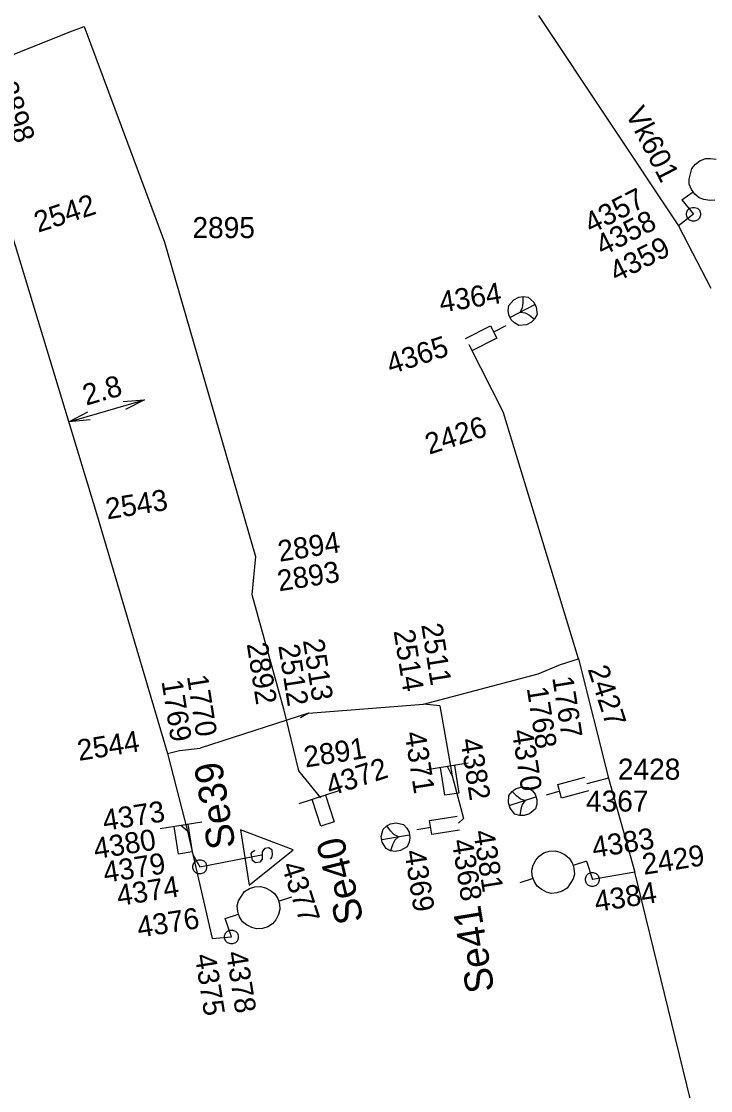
# Model space of a CAD drawing. Extents: x -535557 to -534097, y -1142175 to -1136716.
# Drawn here: x -534945.19 to -534920.6, y -1139009.65 to -1138971.51 of the extents above; entities that cross this region are included whole.
import ezdxf

# ---------------------------------------------------------------- set-up
doc = ezdxf.new("R2010")
doc.units = 0
doc.layers.add('Default', color=7, linetype='Continuous')
doc.layers.add('SS_SZDC', color=7, linetype='Continuous')

# ---------------------------------------------------------------- blocks, each defined once
blk = doc.blocks.new('POINT_DISPLAY')
at = {"layer": 'Default'}
blk.add_line((0, 0), (0, 0), dxfattribs=at)

msp = doc.modelspace()

# ---------------------------------------------------------------- linework, layer by layer
at = {"layer": 'SS_SZDC'}
for p, q in [((-534926.739, -1138971.299), (-534921.739, -1138978.799)), ((-534943.46, -1138971.879), (-534942.949, -1138971.69)), ((-534942.949, -1138971.69), (-534940.09, -1138979.389)), ((-534946.289, -1138973.01), (-534943.46, -1138971.879)), ((-534921.272, -1138976.755), (-534921.14, -1138976.597)), ((-534921.14, -1138976.597), (-534920.978, -1138976.479)), ((-534920.978, -1138976.479), (-534920.787, -1138976.402)), ((-534920.787, -1138976.402), (-534920.607, -1138976.395)), ((-534920.607, -1138976.395), (-534920.397, -1138976.428)), ((-534921.368, -1138977.133), (-534921.272, -1138976.755)), ((-534921.361, -1138977.314), (-534921.368, -1138977.133)), ((-534921.284, -1138977.505), (-534921.361, -1138977.314)), ((-534921.63, -1138977.879), (-534921.225, -1138977.586)), ((-534921.225, -1138977.586), (-534921.284, -1138977.505)), ((-534921.166, -1138977.667), (-534921.225, -1138977.586)), ((-534921.008, -1138977.799), (-534921.166, -1138977.667)), ((-534920.839, -1138977.861), (-534921.008, -1138977.799)), ((-534921.63, -1138977.879), (-534921.21, -1138978.389)), ((-534921.422, -1138978.248), (-534921.351, -1138978.177)), ((-534921.351, -1138978.177), (-534921.245, -1138978.142)), ((-534921.245, -1138978.142), (-534921.174, -1138978.142)), ((-534921.174, -1138978.142), (-534921.068, -1138978.177)), ((-534921.068, -1138978.177), (-534920.997, -1138978.248)), ((-534920.63, -1138977.895), (-534920.839, -1138977.861)), ((-534920.449, -1138977.887), (-534920.63, -1138977.895)), ((-534921.21, -1138978.389), (-534921.739, -1138978.799)), ((-534921.457, -1138978.354), (-534921.422, -1138978.248)), ((-534921.457, -1138978.425), (-534921.457, -1138978.354)), ((-534921.422, -1138978.531), (-534921.457, -1138978.425)), ((-534921.351, -1138978.602), (-534921.422, -1138978.531)), ((-534920.997, -1138978.531), (-534921.068, -1138978.602)), ((-534920.997, -1138978.248), (-534920.962, -1138978.354)), ((-534920.962, -1138978.425), (-534920.997, -1138978.531)), ((-534920.962, -1138978.354), (-534920.962, -1138978.425)), ((-534921.739, -1138978.799), (-534920.59, -1138981.03)), ((-534921.245, -1138978.637), (-534921.351, -1138978.602)), ((-534921.174, -1138978.637), (-534921.245, -1138978.637)), ((-534921.068, -1138978.602), (-534921.174, -1138978.637)), ((-534945.529, -1138979.11), (-534942.51, -1138989.059)), ((-534940.09, -1138979.389), (-534936.84, -1138990.6)), ((-534927.803, -1138981.642), (-534927.626, -1138981.439)), ((-534926.864, -1138981.613), (-534927.755, -1138982.066)), ((-534927.626, -1138981.439), (-534927.447, -1138981.349)), ((-534927.447, -1138981.349), (-534927.291, -1138981.325)), ((-534927.31, -1138981.728), (-534927.289, -1138981.549)), ((-534927.291, -1138981.325), (-534927.112, -1138981.346)), ((-534927.289, -1138981.549), (-534927.291, -1138981.325)), ((-534927.112, -1138981.346), (-534926.909, -1138981.523)), ((-534926.909, -1138981.523), (-534926.819, -1138981.702)), ((-534927.824, -1138981.821), (-534927.803, -1138981.642)), ((-534927.8, -1138981.977), (-534927.824, -1138981.821)), ((-534927.71, -1138982.156), (-534927.8, -1138981.977)), ((-534927.399, -1138981.885), (-534927.31, -1138981.728)), ((-534927.399, -1138981.885), (-534927.22, -1138981.906)), ((-534927.22, -1138981.906), (-534927.062, -1138981.994)), ((-534927.062, -1138981.994), (-534926.882, -1138982.127)), ((-534926.794, -1138981.97), (-534926.882, -1138982.127)), ((-534926.819, -1138981.702), (-534926.794, -1138981.97)), ((-534929.343, -1138982.817), (-534928.452, -1138982.363)), ((-534928.452, -1138982.363), (-534928.225, -1138982.808)), ((-534928.338, -1138982.586), (-534927.893, -1138982.359)), ((-534927.597, -1138982.267), (-534927.71, -1138982.156)), ((-534927.44, -1138982.355), (-534927.597, -1138982.267)), ((-534927.172, -1138982.33), (-534927.44, -1138982.355)), ((-534926.993, -1138982.24), (-534927.172, -1138982.33)), ((-534926.882, -1138982.127), (-534926.993, -1138982.24)), ((-534929.229, -1138983.04), (-534927.989, -1138985.469)), ((-534928.225, -1138982.808), (-534929.116, -1138983.262)), ((-534943.502, -1138985.789), (-534940.798, -1138985.007)), ((-534941.56, -1138985.071), (-534940.798, -1138985.007)), ((-534940.798, -1138985.007), (-534941.477, -1138985.359)), ((-534943.502, -1138985.789), (-534942.823, -1138985.436)), ((-534942.74, -1138985.724), (-534943.502, -1138985.789)), ((-534925.319, -1138994.25), (-534927.989, -1138985.469)), ((-534942.51, -1138989.059), (-534939.979, -1138997.629)), ((-534936.84, -1138990.6), (-534936.97, -1138991.95)), ((-534936.97, -1138991.95), (-534935.84, -1138996.03)), ((-534926.75, -1138994.78), (-534925.96, -1138994.45)), ((-534925.96, -1138994.45), (-534925.319, -1138994.25)), ((-534925.319, -1138994.25), (-534924.239, -1138998.5)), ((-534930.85, -1138995.86), (-534926.75, -1138994.78)), ((-534935.84, -1138996.03), (-534935.31, -1138998.239)), ((-534934.949, -1138996.18), (-534930.85, -1138995.86)), ((-534930.26, -1138995.92), (-534930.85, -1138995.86)), ((-534930.26, -1138995.92), (-534929.819, -1138998.42)), ((-534934.949, -1138996.18), (-534938.819, -1138997.44)), ((-534934.949, -1138996.18), (-534935.229, -1138996.35)), ((-534939.979, -1138997.629), (-534939.55, -1138997.52)), ((-534939.979, -1138997.629), (-534939.26, -1139000.399)), ((-534939.55, -1138997.52), (-534938.819, -1138997.44)), ((-534929.249, -1138997.972), (-534930.73, -1138998.207)), ((-534935.31, -1138998.239), (-534934.52, -1138999.2)), ((-534930.08, -1138999.116), (-534930.236, -1138998.129)), ((-534929.819, -1138998.42), (-534929.989, -1138998.09)), ((-534929.743, -1138998.05), (-534929.586, -1138999.038)), ((-534929.819, -1138998.42), (-534929.42, -1138999.94)), ((-534926.05, -1138998.732), (-534925.085, -1138998.468)), ((-534925.918, -1138999.215), (-534926.05, -1138998.732)), ((-534924.239, -1138998.5), (-534925.02, -1138998.709)), ((-534924.239, -1138998.5), (-534923.3, -1139001.86)), ((-534933.866, -1138998.958), (-534935.293, -1138999.421)), ((-534934.342, -1138999.112), (-534934.033, -1139000.063)), ((-534929.586, -1138999.038), (-534930.08, -1138999.116)), ((-534927.816, -1138999.389), (-534927.798, -1138999.12)), ((-534927.798, -1138999.12), (-534927.686, -1138998.979)), ((-534927.686, -1138998.979), (-534927.559, -1138998.885)), ((-534927.529, -1138999.138), (-534927.686, -1138998.979)), ((-534927.559, -1138998.885), (-534927.369, -1138998.823)), ((-534927.388, -1138999.25), (-534927.529, -1138999.138)), ((-534927.369, -1138998.823), (-534927.1, -1138998.841)), ((-534927.1, -1138998.841), (-534926.959, -1138998.953)), ((-534926.959, -1138998.953), (-534926.865, -1138999.08)), ((-534926.865, -1138999.08), (-534926.803, -1138999.27)), ((-534925.984, -1138998.973), (-534926.466, -1138999.105)), ((-534924.954, -1138998.951), (-534925.918, -1138999.215)), ((-534934.508, -1139000.218), (-534934.817, -1138999.267)), ((-534927.754, -1138999.579), (-534927.816, -1138999.389)), ((-534927.785, -1138999.484), (-534926.834, -1138999.175)), ((-534927.214, -1138999.299), (-534927.388, -1138999.25)), ((-534927.326, -1138999.44), (-534927.375, -1138999.614)), ((-534927.214, -1138999.299), (-534927.326, -1138999.44)), ((-534926.804, -1138999.428), (-534926.853, -1138999.602)), ((-534926.803, -1138999.27), (-534926.804, -1138999.428)), ((-534930.626, -1139000.019), (-534929.639, -1138999.863)), ((-534927.582, -1138999.786), (-534927.754, -1138999.579)), ((-534927.408, -1138999.835), (-534927.582, -1138999.786)), ((-534927.375, -1138999.614), (-534927.408, -1138999.835)), ((-534927.25, -1138999.836), (-534927.408, -1138999.835)), ((-534927.06, -1138999.774), (-534927.25, -1138999.836)), ((-534926.853, -1138999.602), (-534927.06, -1138999.774)), ((-534938.759, -1139000.072), (-534940.24, -1139000.307)), ((-534939.59, -1139001.216), (-534939.746, -1139000.229)), ((-534939.26, -1139000.399), (-534939.5, -1139000.19)), ((-534939.253, -1139000.15), (-534939.096, -1139001.138)), ((-534934.033, -1139000.063), (-534934.508, -1139000.218)), ((-534932.289, -1139000.326), (-534932.157, -1139000.204)), ((-534932.157, -1139000.204), (-534932.016, -1139000.131)), ((-534932.027, -1139000.386), (-534932.157, -1139000.204)), ((-534932.016, -1139000.131), (-534931.819, -1139000.1)), ((-534931.819, -1139000.1), (-534931.556, -1139000.16)), ((-534931.556, -1139000.16), (-534931.434, -1139000.292)), ((-534931.434, -1139000.292), (-534931.361, -1139000.433)), ((-534930.587, -1139000.266), (-534931.081, -1139000.344)), ((-534930.548, -1139000.513), (-534930.626, -1139000.019)), ((-534929.42, -1138999.94), (-534929.6, -1139000.11)), ((-534939.26, -1139000.399), (-534939.079, -1139001.229)), ((-534937.379, -1139000.346), (-534937.066, -1139002.321)), ((-534935.494, -1139001.06), (-534937.379, -1139000.346)), ((-534932.349, -1139000.589), (-534932.289, -1139000.326)), ((-534932.318, -1139000.786), (-534932.349, -1139000.589)), ((-534932.333, -1139000.688), (-534931.346, -1139000.531)), ((-534931.905, -1139000.519), (-534932.027, -1139000.386)), ((-534931.741, -1139000.594), (-534931.905, -1139000.519)), ((-534931.741, -1139000.594), (-534931.873, -1139000.716)), ((-534931.361, -1139000.433), (-534931.33, -1139000.63)), ((-534931.33, -1139000.63), (-534931.356, -1139000.786)), ((-534929.56, -1139000.356), (-534930.548, -1139000.513)), ((-534937.066, -1139002.321), (-534935.494, -1139001.06)), ((-534936.513, -1139001.018), (-534936.596, -1139001.133)), ((-534936.364, -1139000.995), (-534936.513, -1139001.018)), ((-534936.25, -1139001.078), (-534936.364, -1139000.995)), ((-534932.18, -1139001.018), (-534932.318, -1139000.786)), ((-534932.016, -1139001.093), (-534932.18, -1139001.018)), ((-534931.949, -1139000.88), (-534932.016, -1139001.093)), ((-534931.873, -1139000.716), (-534931.949, -1139000.88)), ((-534931.431, -1139000.95), (-534931.663, -1139001.088)), ((-534931.356, -1139000.786), (-534931.431, -1139000.95)), ((-534939.096, -1139001.138), (-534939.59, -1139001.216)), ((-534939.079, -1139001.229), (-534938.38, -1139004.219)), ((-534939.079, -1139001.229), (-534938.829, -1139001.67)), ((-534938.971, -1139001.457), (-534938.865, -1139001.422)), ((-534938.865, -1139001.422), (-534938.794, -1139001.422)), ((-534938.829, -1139001.67), (-534936.63, -1139001.239)), ((-534938.794, -1139001.422), (-534938.688, -1139001.457)), ((-534936.991, -1139001.195), (-534936.949, -1139001.138)), ((-534936.952, -1139001.442), (-534936.991, -1139001.195)), ((-534936.837, -1139001.526), (-534936.952, -1139001.442)), ((-534936.949, -1139001.138), (-534936.858, -1139001.073)), ((-534936.606, -1139001.388), (-534936.689, -1139001.502)), ((-534936.596, -1139001.133), (-534936.606, -1139001.388)), ((-534936.302, -1139001.39), (-534936.26, -1139001.333)), ((-534936.26, -1139001.333), (-534936.227, -1139001.226)), ((-534936.227, -1139001.226), (-534936.25, -1139001.078)), ((-534931.86, -1139001.119), (-534932.016, -1139001.093)), ((-534931.663, -1139001.088), (-534931.86, -1139001.119)), ((-534926.928, -1139001.613), (-534926.832, -1139001.424)), ((-534926.832, -1139001.424), (-534926.72, -1139001.283)), ((-534926.72, -1139001.283), (-534926.545, -1139001.173)), ((-534926.545, -1139001.173), (-534926.355, -1139001.112)), ((-534926.355, -1139001.112), (-534926.149, -1139001.097)), ((-534926.149, -1139001.097), (-534925.976, -1139001.146)), ((-534925.976, -1139001.146), (-534925.787, -1139001.242)), ((-534925.787, -1139001.242), (-534925.645, -1139001.354)), ((-534925.645, -1139001.354), (-534925.536, -1139001.529)), ((-534939.077, -1139001.634), (-534939.042, -1139001.528)), ((-534939.077, -1139001.705), (-534939.077, -1139001.634)), ((-534939.042, -1139001.811), (-534939.077, -1139001.705)), ((-534939.042, -1139001.528), (-534938.971, -1139001.457)), ((-534938.971, -1139001.882), (-534939.042, -1139001.811)), ((-534938.688, -1139001.457), (-534938.617, -1139001.528)), ((-534938.617, -1139001.811), (-534938.688, -1139001.882)), ((-534938.617, -1139001.528), (-534938.582, -1139001.634)), ((-534938.582, -1139001.705), (-534938.617, -1139001.811)), ((-534938.582, -1139001.634), (-534938.582, -1139001.705)), ((-534936.689, -1139001.502), (-534936.837, -1139001.526)), ((-534926.977, -1139001.787), (-534926.928, -1139001.613)), ((-534926.963, -1139001.992), (-534926.977, -1139001.787)), ((-534925.536, -1139001.529), (-534925.505, -1139001.624)), ((-534925.029, -1139001.469), (-534925.505, -1139001.624)), ((-534925.505, -1139001.624), (-534925.474, -1139001.719)), ((-534925.474, -1139001.719), (-534925.46, -1139001.925)), ((-534925.029, -1139001.469), (-534924.819, -1139002.12)), ((-534938.865, -1139001.917), (-534938.971, -1139001.882)), ((-534938.794, -1139001.917), (-534938.865, -1139001.917)), ((-534938.688, -1139001.882), (-534938.794, -1139001.917)), ((-534926.932, -1139002.088), (-534927.407, -1139002.242)), ((-534926.901, -1139002.183), (-534926.963, -1139001.992)), ((-534926.791, -1139002.357), (-534926.901, -1139002.183)), ((-534925.509, -1139002.098), (-534925.717, -1139002.429)), ((-534925.46, -1139001.925), (-534925.509, -1139002.098)), ((-534925.067, -1139002.084), (-534925.032, -1139001.978)), ((-534925.067, -1139002.155), (-534925.067, -1139002.084)), ((-534925.032, -1139002.261), (-534925.067, -1139002.155)), ((-534925.032, -1139001.978), (-534924.961, -1139001.907)), ((-534924.961, -1139001.907), (-534924.855, -1139001.872)), ((-534924.855, -1139001.872), (-534924.784, -1139001.872)), ((-534923.3, -1139001.86), (-534924.819, -1139002.12)), ((-534924.784, -1139001.872), (-534924.678, -1139001.907)), ((-534924.678, -1139001.907), (-534924.607, -1139001.978)), ((-534924.607, -1139001.978), (-534924.572, -1139002.084)), ((-534924.572, -1139002.155), (-534924.607, -1139002.261)), ((-534924.572, -1139002.084), (-534924.572, -1139002.155)), ((-534920.71, -1139012.479), (-534923.3, -1139001.86)), ((-534937.44, -1139002.881), (-534937.232, -1139002.55)), ((-534937.232, -1139002.55), (-534937.058, -1139002.441)), ((-534937.058, -1139002.441), (-534936.867, -1139002.379)), ((-534936.867, -1139002.379), (-534936.662, -1139002.365)), ((-534936.662, -1139002.365), (-534936.488, -1139002.414)), ((-534936.488, -1139002.414), (-534936.299, -1139002.51)), ((-534936.299, -1139002.51), (-534936.158, -1139002.622)), ((-534926.65, -1139002.469), (-534926.791, -1139002.357)), ((-534926.461, -1139002.565), (-534926.65, -1139002.469)), ((-534926.287, -1139002.614), (-534926.461, -1139002.565)), ((-534925.891, -1139002.538), (-534926.082, -1139002.6)), ((-534925.717, -1139002.429), (-534925.891, -1139002.538)), ((-534924.961, -1139002.332), (-534925.032, -1139002.261)), ((-534924.855, -1139002.367), (-534924.961, -1139002.332)), ((-534924.784, -1139002.367), (-534924.855, -1139002.367)), ((-534924.678, -1139002.332), (-534924.784, -1139002.367)), ((-534924.607, -1139002.261), (-534924.678, -1139002.332)), ((-534937.489, -1139003.054), (-534937.44, -1139002.881)), ((-534936.158, -1139002.622), (-534936.048, -1139002.796)), ((-534936.048, -1139002.796), (-534935.986, -1139002.987)), ((-534936.017, -1139002.891), (-534935.542, -1139002.737)), ((-534926.082, -1139002.6), (-534926.287, -1139002.614)), ((-534937.92, -1139003.51), (-534937.444, -1139003.355)), ((-534937.475, -1139003.26), (-534937.489, -1139003.054)), ((-534937.444, -1139003.355), (-534937.475, -1139003.26)), ((-534937.413, -1139003.45), (-534937.444, -1139003.355)), ((-534935.972, -1139003.192), (-534936.021, -1139003.366)), ((-534935.986, -1139002.987), (-534935.972, -1139003.192)), ((-534937.699, -1139004.17), (-534937.92, -1139003.51)), ((-534937.304, -1139003.625), (-534937.413, -1139003.45)), ((-534937.162, -1139003.737), (-534937.304, -1139003.625)), ((-534936.973, -1139003.833), (-534937.162, -1139003.737)), ((-534936.229, -1139003.696), (-534936.404, -1139003.806)), ((-534936.117, -1139003.555), (-534936.229, -1139003.696)), ((-534936.021, -1139003.366), (-534936.117, -1139003.555)), ((-534937.947, -1139004.134), (-534937.912, -1139004.028)), ((-534937.912, -1139004.028), (-534937.841, -1139003.957)), ((-534937.841, -1139003.957), (-534937.735, -1139003.922)), ((-534937.735, -1139003.922), (-534937.664, -1139003.922)), ((-534937.664, -1139003.922), (-534937.558, -1139003.957)), ((-534937.558, -1139003.957), (-534937.487, -1139004.028)), ((-534937.487, -1139004.028), (-534937.452, -1139004.134)), ((-534936.8, -1139003.882), (-534936.973, -1139003.833)), ((-534936.594, -1139003.867), (-534936.8, -1139003.882)), ((-534936.404, -1139003.806), (-534936.594, -1139003.867)), ((-534938.38, -1139004.219), (-534937.699, -1139004.17)), ((-534937.947, -1139004.205), (-534937.947, -1139004.134)), ((-534937.912, -1139004.311), (-534937.947, -1139004.205)), ((-534937.841, -1139004.382), (-534937.912, -1139004.311)), ((-534937.735, -1139004.417), (-534937.841, -1139004.382)), ((-534937.664, -1139004.417), (-534937.735, -1139004.417)), ((-534937.558, -1139004.382), (-534937.664, -1139004.417)), ((-534937.487, -1139004.311), (-534937.558, -1139004.382)), ((-534937.452, -1139004.205), (-534937.487, -1139004.311)), ((-534937.452, -1139004.134), (-534937.452, -1139004.205))]:
    msp.add_line(p, q, dxfattribs=at)

# ---------------------------------------------------------------- block references
for p in [(-534942.949, -1138971.69), (-534943.46, -1138971.879), (-534921.63, -1138977.879), (-534921.21, -1138978.389), (-534921.21, -1138978.389), (-534921.739, -1138978.799), (-534940.09, -1138979.389), (-534927.31, -1138981.84), (-534929.229, -1138983.04), (-534927.989, -1138985.469), (-534942.51, -1138989.059), (-534936.84, -1138990.6), (-534936.97, -1138991.95), (-534925.96, -1138994.45), (-534925.319, -1138994.25), (-534926.75, -1138994.78), (-534935.84, -1138996.03), (-534930.85, -1138995.86), (-534930.26, -1138995.92), (-534935.229, -1138996.35), (-534934.949, -1138996.18), (-534939.979, -1138997.629), (-534939.55, -1138997.52), (-534938.819, -1138997.44), (-534935.31, -1138998.239), (-534929.989, -1138998.09), (-534929.819, -1138998.42), (-534925.02, -1138998.709), (-534924.239, -1138998.5), (-534934.579, -1138999.19), (-534927.31, -1138999.329), (-534939.5, -1139000.19), (-534929.6, -1139000.11), (-534929.42, -1138999.94), (-534939.26, -1139000.399), (-534931.84, -1139000.61), (-534939.079, -1139001.229), (-534936.63, -1139001.239), (-534938.829, -1139001.67), (-534938.829, -1139001.67), (-534925.029, -1139001.469), (-534924.819, -1139002.12), (-534924.819, -1139002.12), (-534923.3, -1139001.86), (-534937.92, -1139003.51), (-534938.38, -1139004.219), (-534937.699, -1139004.17), (-534937.699, -1139004.17)]:
    msp.add_blockref('POINT_DISPLAY', p, dxfattribs=at)

# ---------------------------------------------------------------- texts
for s, height, rotation, p in [('2898', 0.75, 288, (-534946.087, -1138973.783)), ('Vk601', 0.75, 297.3757, (-534923.658, -1138974.79)), ('2542', 0.75, 18, (-534944.596, -1138979.049)), ('4357', 0.75, 27, (-534924.863, -1138979.098)), ('4358', 0.75, 27, (-534924.458, -1138979.889)), ('4359', 0.75, 27, (-534923.961, -1138980.828)), ('4364', 0.75, 9, (-534930.224, -1138981.898)), ('4365', 0.75, 18, (-534932.015, -1138984.107)), ('2.8', 0.75, 16.1296, (-534942.881, -1138985.218)), ('2426', 0.75, 18, (-534930.643, -1138986.97)), ('2543', 0.75, 9, (-534942.131, -1138989.277)), ('2894', 0.75, 9, (-534935.981, -1138990.787)), ('2893', 0.75, 9, (-534935.999, -1138991.842)), ('2511', 0.75, 279, (-534930.926, -1138993.031)), ('2514', 0.75, 279, (-534931.913, -1138993.253)), ('2892', 0.75, 279, (-534937.154, -1138993.717)), ('2512', 0.75, 279, (-534936.029, -1138993.776)), ('2513', 0.75, 279, (-534935.15, -1138993.588)), ('2427', 0.75, 288, (-534924.992, -1138994.613)), ('1770', 0.75, 279, (-534939.29, -1138994.865)), ('1767', 0.75, 279, (-534926.254, -1138994.916)), ('1769', 0.75, 279, (-534940.197, -1138995.047)), ('1768', 0.75, 279, (-534927.163, -1138995.292)), ('2544', 0.75, 9, (-534943.139, -1138997.889)), ('4371', 0.75, 279, (-534931.521, -1138996.891)), ('4370', 0.75, 279, (-534927.695, -1138996.815)), ('2891', 0.75, 9, (-534935.054, -1138998.128)), ('4382', 0.75, 279, (-534929.532, -1138997.133)), ('Se39', 1, 99.3757, (-534937.546, -1139000.948)), ('4372', 0.75, 18, (-534934.173, -1138999.151)), ('4373', 0.75, 9, (-534942.232, -1139000.388)), ('4383', 0.75, 9, (-534924.771, -1139001.351)), ('4380', 0.75, 9, (-534942.555, -1139001.395)), ('Se40', 1, 103.8757, (-534932.968, -1139003.571)), ('4381', 0.75, 279, (-534929.072, -1139000.408)), ('4368', 0.75, 279, (-534929.838, -1139000.73)), ('2429', 0.75, 9, (-534922.978, -1139001.954)), ('4379', 0.75, 9, (-534942.212, -1139002.242)), ('4369', 0.75, 279, (-534931.53, -1139001.113)), ('4377', 0.75, 288, (-534935.924, -1139001.617)), ('4374', 0.75, 9, (-534941.729, -1139003.068)), ('4384', 0.75, 9, (-534924.684, -1139003.281)), ('4376', 0.75, 9, (-534941.003, -1139004.197)), ('Se41', 1, 99.3757, (-534928.312, -1139006.077)), ('4375', 0.75, 279, (-534939.008, -1139004.823)), ('4378', 0.75, 279, (-534937.892, -1139004.729))]:
    msp.add_text(s, height=height, rotation=rotation, dxfattribs=at).set_placement(p)
for s, p in [('2895', (-534939.09, -1138979.239)), ('2428', (-534923.909, -1138998.558)), ('4367', (-534925.046, -1138999.696))]:
    msp.add_text(s, height=0.75, dxfattribs=at).set_placement(p)

doc.saveas('drawing.dxf')
